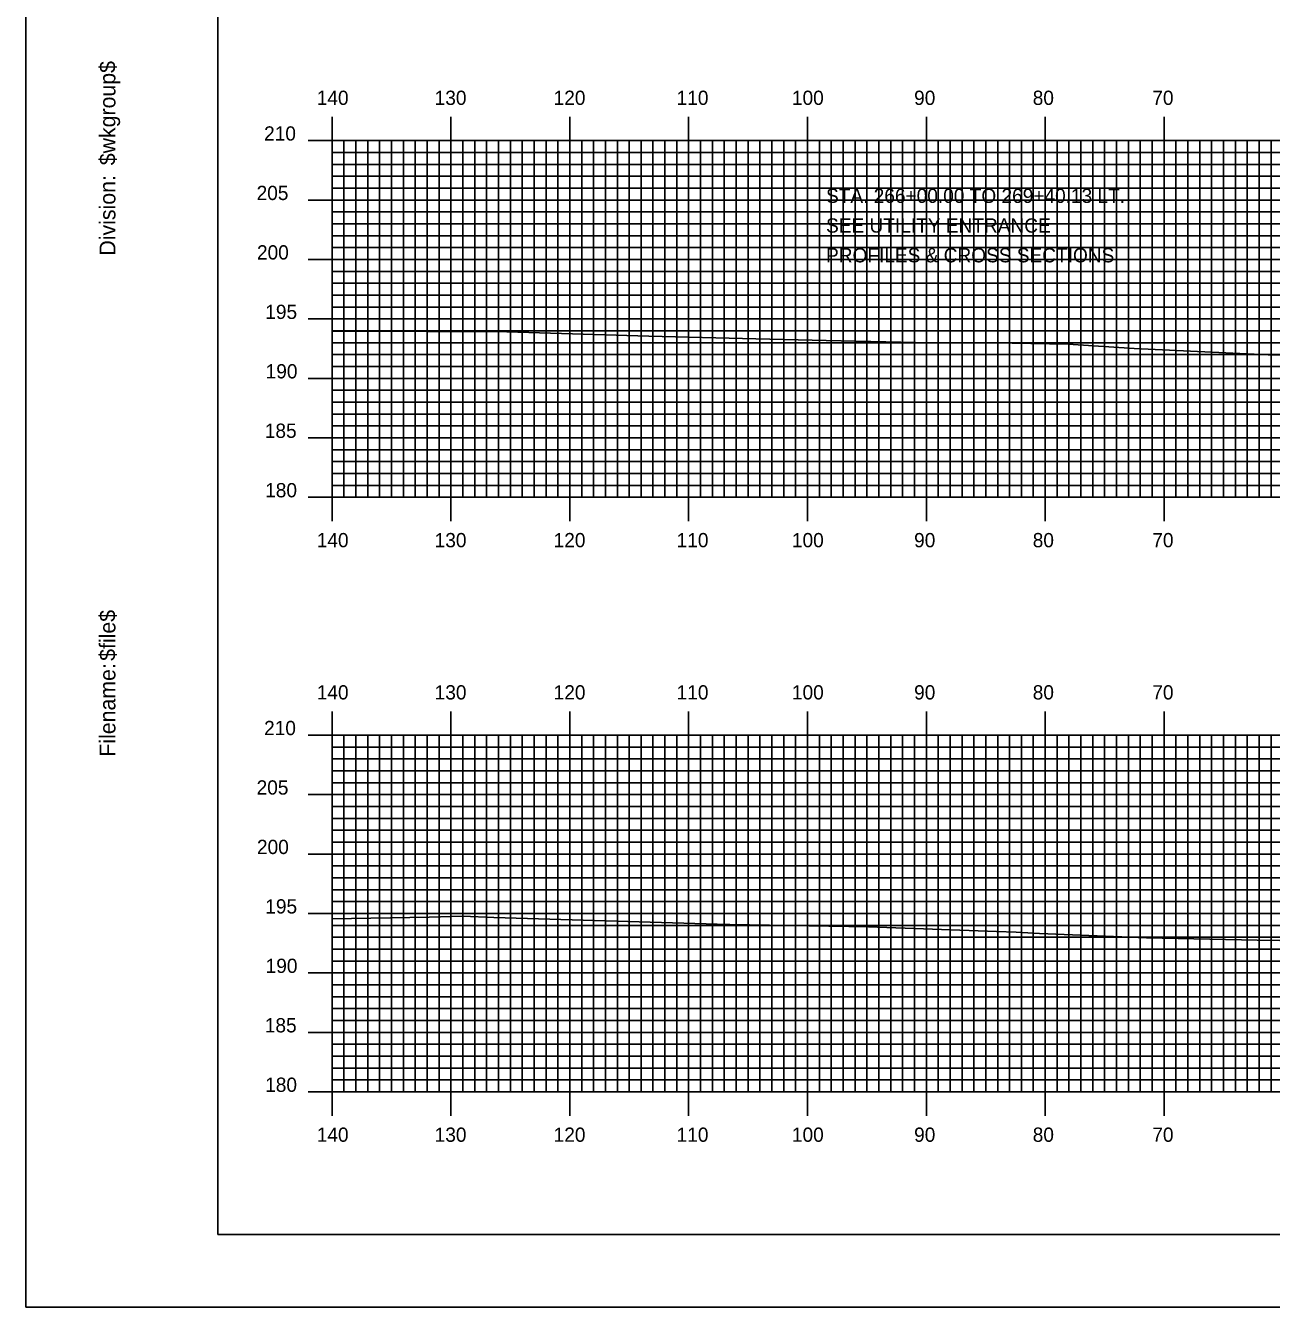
# Model space of a CAD drawing. Extents: x 1807438 to 1807782, y 442591 to 442811.
# Drawn here: x 1807438.5 to 1807543.3, y 442590.5 to 442698.3 of the extents above; entities that cross this region are included whole.
import ezdxf

# ---------------------------------------------------------------- set-up
doc = ezdxf.new("R2010")
doc.units = 0
for name, color, linetype in [('BORDER', 7, 'Continuous'), ('D_Text_Standard', 7, 'Continuous'), ('H_V ANNOTATION', 7, 'Continuous'), ('MAJOR', 7, 'Continuous'), ('MINOR', 7, 'Continuous'), ('PLOT BOUNDARY', 7, 'Continuous'), ('S_Roadway_Centerline', 7, 'Continuous')]:
    doc.layers.add(name, color=color, linetype=linetype)

msp = doc.modelspace()

# ---------------------------------------------------------------- linework, layer by layer
at = {"layer": 'BORDER'}
msp.add_lwpolyline([(1807454.67, 442596.67), (1807774.67, 442596.67), (1807774.67, 442806.67), (1807454.67, 442806.67)], close=True, dxfattribs=at)
at = {"layer": 'MAJOR'}
for p, q in [((1807464.27, 442690.67), (1807464.27, 442688.67)), ((1807474.27, 442690.67), (1807474.27, 442688.67)), ((1807484.27, 442690.67), (1807484.27, 442688.67)), ((1807494.27, 442690.67), (1807494.27, 442688.67)), ((1807504.27, 442690.67), (1807504.27, 442688.67)), ((1807514.27, 442690.67), (1807514.27, 442688.67)), ((1807524.27, 442690.67), (1807524.27, 442688.67)), ((1807534.27, 442690.67), (1807534.27, 442688.67)), ((1807462.27, 442688.67), (1807464.27, 442688.67)), ((1807464.27, 442688.67), (1807744.27, 442688.67)), ((1807464.27, 442658.67), (1807464.27, 442688.67)), ((1807464.27, 442658.67), (1807464.27, 442688.67)), ((1807464.27, 442688.67), (1807744.27, 442688.67)), ((1807474.27, 442658.67), (1807474.27, 442688.67)), ((1807484.27, 442658.67), (1807484.27, 442688.67)), ((1807494.27, 442658.67), (1807494.27, 442688.67)), ((1807504.27, 442658.67), (1807504.27, 442688.67)), ((1807514.27, 442658.67), (1807514.27, 442688.67)), ((1807524.27, 442658.67), (1807524.27, 442688.67)), ((1807534.27, 442658.67), (1807534.27, 442688.67)), ((1807462.27, 442683.67), (1807464.27, 442683.67)), ((1807464.27, 442683.67), (1807744.27, 442683.67)), ((1807462.27, 442678.67), (1807464.27, 442678.67)), ((1807464.27, 442678.67), (1807744.27, 442678.67)), ((1807462.27, 442673.67), (1807464.27, 442673.67)), ((1807464.27, 442673.67), (1807744.27, 442673.67)), ((1807462.27, 442668.67), (1807464.27, 442668.67)), ((1807464.27, 442668.67), (1807744.27, 442668.67)), ((1807462.27, 442663.67), (1807464.27, 442663.67)), ((1807464.27, 442663.67), (1807744.27, 442663.67)), ((1807462.27, 442658.67), (1807464.27, 442658.67)), ((1807464.27, 442658.67), (1807744.27, 442658.67)), ((1807464.27, 442658.67), (1807744.27, 442658.67)), ((1807464.27, 442656.66), (1807464.27, 442658.67)), ((1807474.27, 442656.66), (1807474.27, 442658.67)), ((1807484.27, 442656.66), (1807484.27, 442658.67)), ((1807494.27, 442656.66), (1807494.27, 442658.67)), ((1807504.27, 442656.66), (1807504.27, 442658.67)), ((1807514.27, 442656.66), (1807514.27, 442658.67)), ((1807524.27, 442656.66), (1807524.27, 442658.67)), ((1807534.27, 442656.66), (1807534.27, 442658.67)), ((1807464.27, 442640.67), (1807464.27, 442638.67)), ((1807474.27, 442640.67), (1807474.27, 442638.67)), ((1807484.27, 442640.67), (1807484.27, 442638.67)), ((1807494.27, 442640.67), (1807494.27, 442638.67)), ((1807504.27, 442640.67), (1807504.27, 442638.67)), ((1807514.27, 442640.67), (1807514.27, 442638.67)), ((1807524.27, 442640.67), (1807524.27, 442638.67)), ((1807534.27, 442640.67), (1807534.27, 442638.67)), ((1807462.27, 442638.67), (1807464.27, 442638.67)), ((1807464.27, 442638.67), (1807744.27, 442638.67)), ((1807464.27, 442608.67), (1807464.27, 442638.67)), ((1807464.27, 442608.67), (1807464.27, 442638.67)), ((1807464.27, 442638.67), (1807744.27, 442638.67)), ((1807474.27, 442608.67), (1807474.27, 442638.67)), ((1807484.27, 442608.67), (1807484.27, 442638.67)), ((1807494.27, 442608.67), (1807494.27, 442638.67)), ((1807504.27, 442608.67), (1807504.27, 442638.67)), ((1807514.27, 442608.67), (1807514.27, 442638.67)), ((1807524.27, 442608.67), (1807524.27, 442638.67)), ((1807534.27, 442608.67), (1807534.27, 442638.67)), ((1807462.27, 442633.67), (1807464.27, 442633.67)), ((1807464.27, 442633.67), (1807744.27, 442633.67)), ((1807462.27, 442628.67), (1807464.27, 442628.67)), ((1807464.27, 442628.67), (1807744.27, 442628.67)), ((1807462.27, 442623.67), (1807464.27, 442623.67)), ((1807464.27, 442623.67), (1807744.27, 442623.67)), ((1807462.27, 442618.67), (1807464.27, 442618.67)), ((1807464.27, 442618.67), (1807744.27, 442618.67)), ((1807462.27, 442613.67), (1807464.27, 442613.67)), ((1807464.27, 442613.67), (1807744.27, 442613.67)), ((1807462.27, 442608.67), (1807464.27, 442608.67)), ((1807464.27, 442608.67), (1807744.27, 442608.67)), ((1807464.27, 442608.67), (1807744.27, 442608.67)), ((1807464.27, 442606.66), (1807464.27, 442608.67)), ((1807474.27, 442606.66), (1807474.27, 442608.67)), ((1807484.27, 442606.66), (1807484.27, 442608.67)), ((1807494.27, 442606.66), (1807494.27, 442608.67)), ((1807504.27, 442606.66), (1807504.27, 442608.67)), ((1807514.27, 442606.66), (1807514.27, 442608.67)), ((1807524.27, 442606.66), (1807524.27, 442608.67)), ((1807534.27, 442606.66), (1807534.27, 442608.67))]:
    msp.add_line(p, q, dxfattribs=at)
at = {"layer": 'MINOR'}
for p, q in [((1807465.27, 442658.67), (1807465.27, 442688.67)), ((1807466.27, 442658.67), (1807466.27, 442688.67)), ((1807467.27, 442658.67), (1807467.27, 442688.67)), ((1807468.27, 442658.67), (1807468.27, 442688.67)), ((1807469.27, 442658.67), (1807469.27, 442688.67)), ((1807470.27, 442658.67), (1807470.27, 442688.67)), ((1807471.27, 442658.67), (1807471.27, 442688.67)), ((1807472.27, 442658.67), (1807472.27, 442688.67)), ((1807473.27, 442658.67), (1807473.27, 442688.67)), ((1807475.27, 442658.67), (1807475.27, 442688.67)), ((1807476.27, 442658.67), (1807476.27, 442688.67)), ((1807477.27, 442658.67), (1807477.27, 442688.67)), ((1807478.27, 442658.67), (1807478.27, 442688.67)), ((1807479.27, 442658.67), (1807479.27, 442688.67)), ((1807480.27, 442658.67), (1807480.27, 442688.67)), ((1807481.27, 442658.67), (1807481.27, 442688.67)), ((1807482.27, 442658.67), (1807482.27, 442688.67)), ((1807483.27, 442658.67), (1807483.27, 442688.67)), ((1807485.27, 442658.67), (1807485.27, 442688.67)), ((1807486.27, 442658.67), (1807486.27, 442688.67)), ((1807487.27, 442658.67), (1807487.27, 442688.67)), ((1807488.27, 442658.67), (1807488.27, 442688.67)), ((1807489.27, 442658.67), (1807489.27, 442688.67)), ((1807490.27, 442658.67), (1807490.27, 442688.67)), ((1807491.27, 442658.67), (1807491.27, 442688.67)), ((1807492.27, 442658.67), (1807492.27, 442688.67)), ((1807493.27, 442658.67), (1807493.27, 442688.67)), ((1807495.27, 442658.67), (1807495.27, 442688.67)), ((1807496.27, 442658.67), (1807496.27, 442688.67)), ((1807497.27, 442658.67), (1807497.27, 442688.67)), ((1807498.27, 442658.67), (1807498.27, 442688.67)), ((1807499.27, 442658.67), (1807499.27, 442688.67)), ((1807500.27, 442658.67), (1807500.27, 442688.67)), ((1807501.27, 442658.67), (1807501.27, 442688.67)), ((1807502.27, 442658.67), (1807502.27, 442688.67)), ((1807503.27, 442658.67), (1807503.27, 442688.67)), ((1807505.27, 442658.67), (1807505.27, 442688.67)), ((1807506.27, 442658.67), (1807506.27, 442688.67)), ((1807507.27, 442658.67), (1807507.27, 442688.67)), ((1807508.27, 442658.67), (1807508.27, 442688.67)), ((1807509.27, 442658.67), (1807509.27, 442688.67)), ((1807510.27, 442658.67), (1807510.27, 442688.67)), ((1807511.27, 442658.67), (1807511.27, 442688.67)), ((1807512.27, 442658.67), (1807512.27, 442688.67)), ((1807513.27, 442658.67), (1807513.27, 442688.67)), ((1807515.27, 442658.67), (1807515.27, 442688.67)), ((1807516.27, 442658.67), (1807516.27, 442688.67)), ((1807517.27, 442658.67), (1807517.27, 442688.67)), ((1807518.27, 442658.67), (1807518.27, 442688.67)), ((1807519.27, 442658.67), (1807519.27, 442688.67)), ((1807520.27, 442658.67), (1807520.27, 442688.67)), ((1807521.27, 442658.67), (1807521.27, 442688.67)), ((1807522.27, 442658.67), (1807522.27, 442688.67)), ((1807523.27, 442658.67), (1807523.27, 442688.67)), ((1807525.27, 442658.67), (1807525.27, 442688.67)), ((1807526.27, 442658.67), (1807526.27, 442688.67)), ((1807527.27, 442658.67), (1807527.27, 442688.67)), ((1807528.27, 442658.67), (1807528.27, 442688.67)), ((1807529.27, 442658.67), (1807529.27, 442688.67)), ((1807530.27, 442658.67), (1807530.27, 442688.67)), ((1807531.27, 442658.67), (1807531.27, 442688.67)), ((1807532.27, 442658.67), (1807532.27, 442688.67)), ((1807533.27, 442658.67), (1807533.27, 442688.67)), ((1807535.27, 442658.67), (1807535.27, 442688.67)), ((1807536.27, 442658.67), (1807536.27, 442688.67)), ((1807537.27, 442658.67), (1807537.27, 442688.67)), ((1807538.27, 442658.67), (1807538.27, 442688.67)), ((1807539.27, 442658.67), (1807539.27, 442688.67)), ((1807540.27, 442658.67), (1807540.27, 442688.67)), ((1807541.27, 442658.67), (1807541.27, 442688.67)), ((1807542.27, 442658.67), (1807542.27, 442688.67)), ((1807543.27, 442658.67), (1807543.27, 442688.67)), ((1807464.27, 442687.67), (1807744.27, 442687.67)), ((1807464.27, 442687.67), (1807466.28, 442687.67)), ((1807464.27, 442686.67), (1807744.27, 442686.67)), ((1807464.27, 442686.67), (1807466.28, 442686.67)), ((1807464.27, 442685.67), (1807744.27, 442685.67)), ((1807464.27, 442685.67), (1807466.28, 442685.67)), ((1807464.27, 442684.67), (1807744.27, 442684.67)), ((1807464.27, 442684.67), (1807466.28, 442684.67)), ((1807464.27, 442682.67), (1807744.27, 442682.67)), ((1807464.27, 442682.67), (1807466.28, 442682.67)), ((1807464.27, 442681.67), (1807744.27, 442681.67)), ((1807464.27, 442681.67), (1807466.28, 442681.67)), ((1807464.27, 442680.67), (1807744.27, 442680.67)), ((1807464.27, 442680.67), (1807466.28, 442680.67)), ((1807464.27, 442679.67), (1807744.27, 442679.67)), ((1807464.27, 442679.67), (1807466.28, 442679.67)), ((1807464.27, 442677.67), (1807744.27, 442677.67)), ((1807464.27, 442677.67), (1807466.28, 442677.67)), ((1807464.27, 442676.67), (1807744.27, 442676.67)), ((1807464.27, 442676.67), (1807466.28, 442676.67)), ((1807464.27, 442675.67), (1807744.27, 442675.67)), ((1807464.27, 442675.67), (1807466.28, 442675.67)), ((1807464.27, 442674.67), (1807744.27, 442674.67)), ((1807464.27, 442674.67), (1807466.28, 442674.67)), ((1807464.27, 442672.67), (1807744.27, 442672.67)), ((1807464.27, 442672.67), (1807466.28, 442672.67)), ((1807464.27, 442671.67), (1807744.27, 442671.67)), ((1807464.27, 442671.67), (1807466.28, 442671.67)), ((1807464.27, 442670.67), (1807744.27, 442670.67)), ((1807464.27, 442670.67), (1807466.28, 442670.67)), ((1807464.27, 442669.67), (1807744.27, 442669.67)), ((1807464.27, 442669.67), (1807466.28, 442669.67)), ((1807464.27, 442667.67), (1807744.27, 442667.67)), ((1807464.27, 442667.67), (1807466.28, 442667.67)), ((1807464.27, 442666.67), (1807744.27, 442666.67)), ((1807464.27, 442666.67), (1807466.28, 442666.67)), ((1807464.27, 442665.67), (1807744.27, 442665.67)), ((1807464.27, 442665.67), (1807466.28, 442665.67)), ((1807464.27, 442664.67), (1807744.27, 442664.67)), ((1807464.27, 442664.67), (1807466.28, 442664.67)), ((1807464.27, 442662.67), (1807744.27, 442662.67)), ((1807464.27, 442662.67), (1807466.28, 442662.67)), ((1807464.27, 442661.67), (1807744.27, 442661.67)), ((1807464.27, 442661.67), (1807466.28, 442661.67)), ((1807464.27, 442660.67), (1807744.27, 442660.67)), ((1807464.27, 442660.67), (1807466.28, 442660.67)), ((1807464.27, 442659.67), (1807744.27, 442659.67)), ((1807464.27, 442659.67), (1807466.28, 442659.67)), ((1807465.27, 442608.67), (1807465.27, 442638.67)), ((1807466.27, 442608.67), (1807466.27, 442638.67)), ((1807467.27, 442608.67), (1807467.27, 442638.67)), ((1807468.27, 442608.67), (1807468.27, 442638.67)), ((1807469.27, 442608.67), (1807469.27, 442638.67)), ((1807470.27, 442608.67), (1807470.27, 442638.67)), ((1807471.27, 442608.67), (1807471.27, 442638.67)), ((1807472.27, 442608.67), (1807472.27, 442638.67)), ((1807473.27, 442608.67), (1807473.27, 442638.67)), ((1807475.27, 442608.67), (1807475.27, 442638.67)), ((1807476.27, 442608.67), (1807476.27, 442638.67)), ((1807477.27, 442608.67), (1807477.27, 442638.67)), ((1807478.27, 442608.67), (1807478.27, 442638.67)), ((1807479.27, 442608.67), (1807479.27, 442638.67)), ((1807480.27, 442608.67), (1807480.27, 442638.67)), ((1807481.27, 442608.67), (1807481.27, 442638.67)), ((1807482.27, 442608.67), (1807482.27, 442638.67)), ((1807483.27, 442608.67), (1807483.27, 442638.67)), ((1807485.27, 442608.67), (1807485.27, 442638.67)), ((1807486.27, 442608.67), (1807486.27, 442638.67)), ((1807487.27, 442608.67), (1807487.27, 442638.67)), ((1807488.27, 442608.67), (1807488.27, 442638.67)), ((1807489.27, 442608.67), (1807489.27, 442638.67)), ((1807490.27, 442608.67), (1807490.27, 442638.67)), ((1807491.27, 442608.67), (1807491.27, 442638.67)), ((1807492.27, 442608.67), (1807492.27, 442638.67)), ((1807493.27, 442608.67), (1807493.27, 442638.67)), ((1807495.27, 442608.67), (1807495.27, 442638.67)), ((1807496.27, 442608.67), (1807496.27, 442638.67)), ((1807497.27, 442608.67), (1807497.27, 442638.67)), ((1807498.27, 442608.67), (1807498.27, 442638.67)), ((1807499.27, 442608.67), (1807499.27, 442638.67)), ((1807500.27, 442608.67), (1807500.27, 442638.67)), ((1807501.27, 442608.67), (1807501.27, 442638.67)), ((1807502.27, 442608.67), (1807502.27, 442638.67)), ((1807503.27, 442608.67), (1807503.27, 442638.67)), ((1807505.27, 442608.67), (1807505.27, 442638.67)), ((1807506.27, 442608.67), (1807506.27, 442638.67)), ((1807507.27, 442608.67), (1807507.27, 442638.67)), ((1807508.27, 442608.67), (1807508.27, 442638.67)), ((1807509.27, 442608.67), (1807509.27, 442638.67)), ((1807510.27, 442608.67), (1807510.27, 442638.67)), ((1807511.27, 442608.67), (1807511.27, 442638.67)), ((1807512.27, 442608.67), (1807512.27, 442638.67)), ((1807513.27, 442608.67), (1807513.27, 442638.67)), ((1807515.27, 442608.67), (1807515.27, 442638.67)), ((1807516.27, 442608.67), (1807516.27, 442638.67)), ((1807517.27, 442608.67), (1807517.27, 442638.67)), ((1807518.27, 442608.67), (1807518.27, 442638.67)), ((1807519.27, 442608.67), (1807519.27, 442638.67)), ((1807520.27, 442608.67), (1807520.27, 442638.67)), ((1807521.27, 442608.67), (1807521.27, 442638.67)), ((1807522.27, 442608.67), (1807522.27, 442638.67)), ((1807523.27, 442608.67), (1807523.27, 442638.67)), ((1807525.27, 442608.67), (1807525.27, 442638.67)), ((1807526.27, 442608.67), (1807526.27, 442638.67)), ((1807527.27, 442608.67), (1807527.27, 442638.67)), ((1807528.27, 442608.67), (1807528.27, 442638.67)), ((1807529.27, 442608.67), (1807529.27, 442638.67)), ((1807530.27, 442608.67), (1807530.27, 442638.67)), ((1807531.27, 442608.67), (1807531.27, 442638.67)), ((1807532.27, 442608.67), (1807532.27, 442638.67)), ((1807533.27, 442608.67), (1807533.27, 442638.67)), ((1807535.27, 442608.67), (1807535.27, 442638.67)), ((1807536.27, 442608.67), (1807536.27, 442638.67)), ((1807537.27, 442608.67), (1807537.27, 442638.67)), ((1807538.27, 442608.67), (1807538.27, 442638.67)), ((1807539.27, 442608.67), (1807539.27, 442638.67)), ((1807540.27, 442608.67), (1807540.27, 442638.67)), ((1807541.27, 442608.67), (1807541.27, 442638.67)), ((1807542.27, 442608.67), (1807542.27, 442638.67)), ((1807543.27, 442608.67), (1807543.27, 442638.67)), ((1807464.27, 442637.67), (1807744.27, 442637.67)), ((1807464.27, 442637.67), (1807466.28, 442637.67)), ((1807464.27, 442636.67), (1807744.27, 442636.67)), ((1807464.27, 442636.67), (1807466.28, 442636.67)), ((1807464.27, 442635.67), (1807744.27, 442635.67)), ((1807464.27, 442635.67), (1807466.28, 442635.67)), ((1807464.27, 442634.67), (1807744.27, 442634.67)), ((1807464.27, 442634.67), (1807466.28, 442634.67)), ((1807464.27, 442632.67), (1807744.27, 442632.67)), ((1807464.27, 442632.67), (1807466.28, 442632.67)), ((1807464.27, 442631.67), (1807744.27, 442631.67)), ((1807464.27, 442631.67), (1807466.28, 442631.67)), ((1807464.27, 442630.67), (1807744.27, 442630.67)), ((1807464.27, 442630.67), (1807466.28, 442630.67)), ((1807464.27, 442629.67), (1807744.27, 442629.67)), ((1807464.27, 442629.67), (1807466.28, 442629.67)), ((1807464.27, 442627.67), (1807744.27, 442627.67)), ((1807464.27, 442627.67), (1807466.28, 442627.67)), ((1807464.27, 442626.67), (1807744.27, 442626.67)), ((1807464.27, 442626.67), (1807466.28, 442626.67)), ((1807464.27, 442625.67), (1807744.27, 442625.67)), ((1807464.27, 442625.67), (1807466.28, 442625.67)), ((1807464.27, 442624.67), (1807744.27, 442624.67)), ((1807464.27, 442624.67), (1807466.28, 442624.67)), ((1807464.27, 442622.67), (1807744.27, 442622.67)), ((1807464.27, 442622.67), (1807466.28, 442622.67)), ((1807464.27, 442621.67), (1807744.27, 442621.67)), ((1807464.27, 442621.67), (1807466.28, 442621.67)), ((1807464.27, 442620.67), (1807744.27, 442620.67)), ((1807464.27, 442620.67), (1807466.28, 442620.67)), ((1807464.27, 442619.67), (1807744.27, 442619.67)), ((1807464.27, 442619.67), (1807466.28, 442619.67)), ((1807464.27, 442617.67), (1807744.27, 442617.67)), ((1807464.27, 442617.67), (1807466.28, 442617.67)), ((1807464.27, 442616.67), (1807744.27, 442616.67)), ((1807464.27, 442616.67), (1807466.28, 442616.67)), ((1807464.27, 442615.67), (1807744.27, 442615.67)), ((1807464.27, 442615.67), (1807466.28, 442615.67)), ((1807464.27, 442614.67), (1807744.27, 442614.67)), ((1807464.27, 442614.67), (1807466.28, 442614.67)), ((1807464.27, 442612.67), (1807744.27, 442612.67)), ((1807464.27, 442612.67), (1807466.28, 442612.67)), ((1807464.27, 442611.67), (1807744.27, 442611.67)), ((1807464.27, 442611.67), (1807466.28, 442611.67)), ((1807464.27, 442610.67), (1807744.27, 442610.67)), ((1807464.27, 442610.67), (1807466.28, 442610.67)), ((1807464.27, 442609.67), (1807744.27, 442609.67)), ((1807464.27, 442609.67), (1807466.28, 442609.67))]:
    msp.add_line(p, q, dxfattribs=at)
at = {"layer": 'PLOT BOUNDARY'}
msp.add_lwpolyline([(1807438.49, 442590.55), (1807778.49, 442590.55), (1807778.49, 442810.55), (1807438.49, 442810.55)], close=True, dxfattribs=at)
at = {"layer": 'S_Roadway_Centerline'}
for points in [[(1807464.27, 442672.65), (1807472.34, 442672.62), (1807477.44, 442672.61), (1807478.97, 442672.58), (1807490.93, 442672.21), (1807499.92, 442672.01), (1807505.84, 442671.85), (1807514.63, 442671.65), (1807521.49, 442671.64), (1807526.19, 442671.56), (1807531.76, 442671.18), (1807543.03, 442670.64), (1807558.83, 442670.39)], [(1807464.27, 442623.22), (1807472.45, 442623.37), (1807475.27, 442623.46), (1807477.89, 442623.34), (1807497.61, 442622.75), (1807497.73, 442622.75), (1807509.41, 442622.55), (1807520.16, 442622.16), (1807521.84, 442622.11), (1807523.78, 442621.99), (1807532.79, 442621.63), (1807542.11, 442621.43), (1807545.92, 442621.36)]]:
    msp.add_lwpolyline(points, dxfattribs=at)

# ---------------------------------------------------------------- texts
at = {"layer": 'BORDER'}
for s, p in [('$wkgroup$', (1807446.04, 442686.6)), ('Division:', (1807446.04, 442679)), ('$file$', (1807446.04, 442644.92)), ('Filename:', (1807446.04, 442636.86))]:
    msp.add_text(s, height=1.339, rotation=90, dxfattribs=at).set_placement(p)
at = {"layer": 'D_Text_Standard'}
for s, p in [('STA. 266+00.00 TO 269+40.13 LT. ', (1807505.83, 442683.43)), ('SEE UTILITY ENTRANCE', (1807505.83, 442680.93)), ('PROFILES & CROSS SECTIONS', (1807505.83, 442678.43))]:
    msp.add_text(s, height=1.2, dxfattribs=at).set_placement(p)
at = {"layer": 'H_V ANNOTATION'}
for s, p in [('140', (1807462.98, 442691.67)), ('130', (1807472.9, 442691.67)), ('120', (1807482.91, 442691.67)), ('110', (1807493.26, 442691.67)), ('100', (1807502.96, 442691.67)), ('90', (1807513.24, 442691.67)), ('80', (1807523.22, 442691.67)), ('70', (1807533.28, 442691.67)), ('210', (1807458.55, 442688.67)), ('205', (1807457.92, 442683.67)), ('200', (1807457.95, 442678.67)), ('195', (1807458.65, 442673.67)), ('190', (1807458.68, 442668.67)), ('185', (1807458.61, 442663.67)), ('180', (1807458.64, 442658.67)), ('140', (1807462.98, 442654.47)), ('130', (1807472.9, 442654.47)), ('120', (1807482.91, 442654.47)), ('110', (1807493.26, 442654.47)), ('100', (1807502.96, 442654.47)), ('90', (1807513.24, 442654.47)), ('80', (1807523.22, 442654.47)), ('70', (1807533.28, 442654.47)), ('140', (1807462.98, 442641.67)), ('130', (1807472.9, 442641.67)), ('120', (1807482.91, 442641.67)), ('110', (1807493.26, 442641.67)), ('100', (1807502.96, 442641.67)), ('90', (1807513.24, 442641.67)), ('80', (1807523.22, 442641.67)), ('70', (1807533.28, 442641.67)), ('210', (1807458.55, 442638.67)), ('205', (1807457.92, 442633.67)), ('200', (1807457.95, 442628.67)), ('195', (1807458.65, 442623.67)), ('190', (1807458.68, 442618.67)), ('185', (1807458.61, 442613.67)), ('180', (1807458.64, 442608.67)), ('140', (1807462.98, 442604.47)), ('130', (1807472.9, 442604.47)), ('120', (1807482.91, 442604.47)), ('110', (1807493.26, 442604.47)), ('100', (1807502.96, 442604.47)), ('90', (1807513.24, 442604.47)), ('80', (1807523.22, 442604.47)), ('70', (1807533.28, 442604.47))]:
    msp.add_text(s, height=1.2, dxfattribs=at).set_placement(p)
at = {"layer": 'MAJOR'}
for p in [(1807464.26, 442658.67), (1807464.26, 442608.67)]:
    msp.add_text('-', height=0.012, dxfattribs=at).set_placement(p)

doc.saveas('drawing.dxf')
